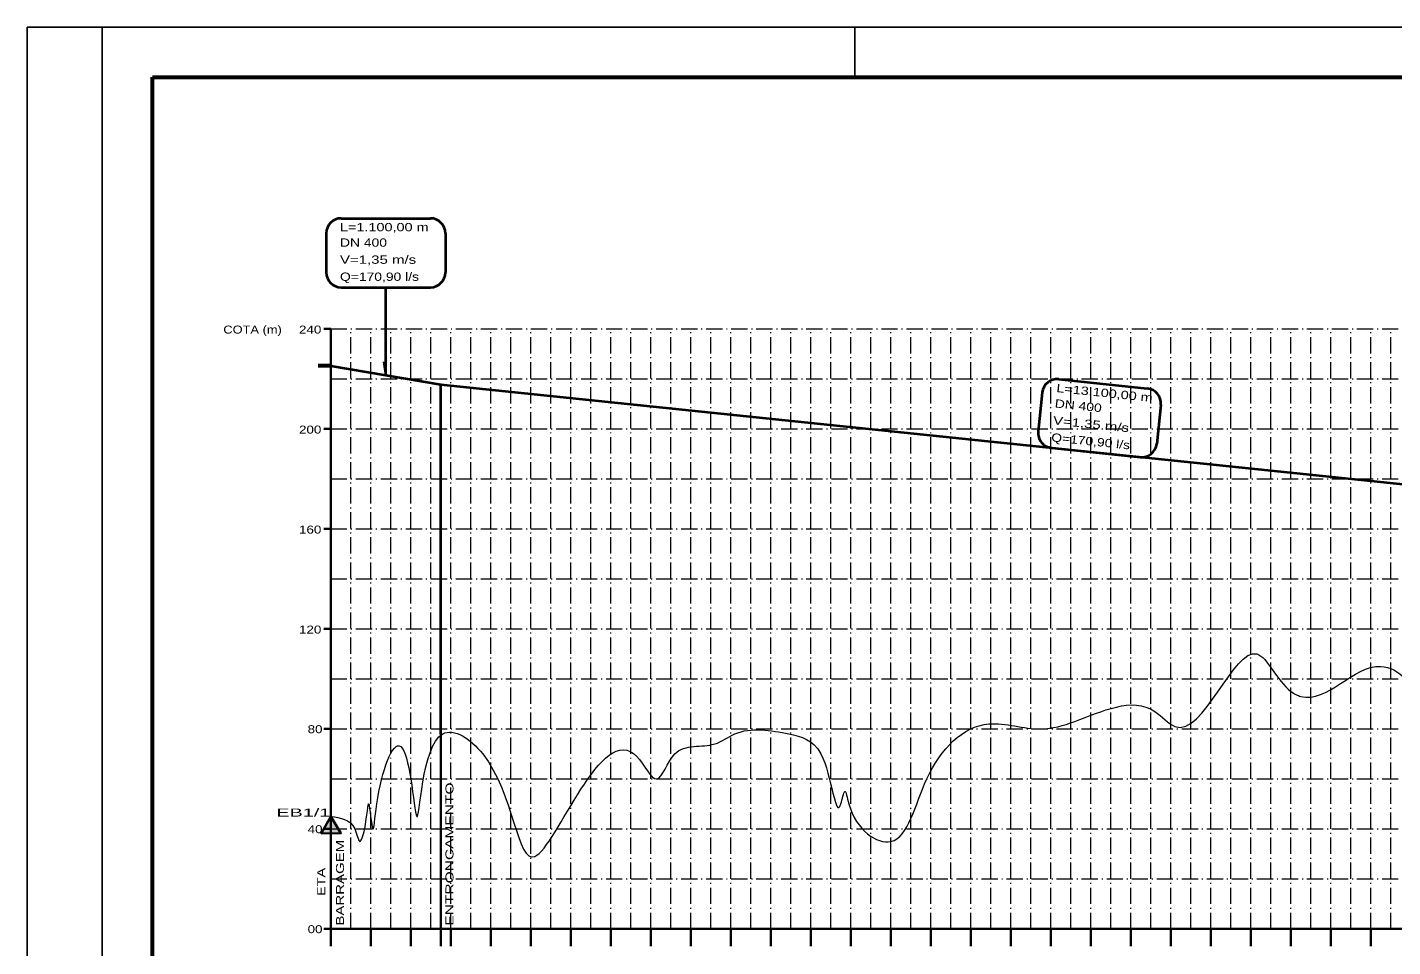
# Model space of a CAD drawing. Extents: x 0 to 1772, y 0 to 1188.
# Drawn here: x 0 to 546, y 820 to 1188 of the extents above; entities that cross this region are included whole.
import ezdxf
from ezdxf.enums import TextEntityAlignment as Align

# ---------------------------------------------------------------- set-up
doc = ezdxf.new("R2010")
doc.units = 0
doc.header["$LTSCALE"] = 1.3
doc.header["$PDMODE"] = 32
doc.header["$PDSIZE"] = 0.65
doc.linetypes.add('DOT_DASHED', pattern=[7.7, 5, -1.2, 0.3, -1.2])
for name, color, linetype, lineweight in [('1', 7, 'DOT_DASHED', 13), ('24', 7, 'Continuous', 35), ('55', 7, 'Continuous', 13), ('62', 7, 'Continuous', 13), ('63', 7, 'Continuous', 25), ('9', 7, 'Continuous', 40)]:
    doc.layers.add(name, color=color, linetype=linetype, lineweight=lineweight)

msp = doc.modelspace()

# ---------------------------------------------------------------- hatches: boundary and pattern name
at = {"layer": '62'}
msp.add_hatch(color=256, dxfattribs=at).paths.add_polyline_path([(121.273, 872.22), (125.219, 865.482), (117.41, 865.434)])

# ---------------------------------------------------------------- linework, layer by layer
at = {"layer": '1'}
for p, q in [((121.175, 1067.213), (1313.175, 1067.213)), ((129.175, 827.213), (129.175, 1067.213)), ((137.175, 827.213), (137.175, 1067.213)), ((145.175, 827.213), (145.175, 1067.213)), ((153.175, 827.213), (153.175, 1067.213)), ((161.175, 827.213), (161.175, 1067.213)), ((169.175, 827.213), (169.175, 1067.213)), ((177.175, 827.213), (177.175, 1067.213)), ((185.175, 827.213), (185.175, 1067.213)), ((193.175, 827.213), (193.175, 1067.213)), ((201.175, 827.213), (201.175, 1067.213)), ((209.175, 827.213), (209.175, 1067.213)), ((217.175, 827.213), (217.175, 1067.213)), ((225.175, 827.213), (225.175, 1067.213)), ((233.175, 827.213), (233.175, 1067.213)), ((241.175, 827.213), (241.175, 1067.213)), ((249.175, 827.213), (249.175, 1067.213)), ((257.175, 827.213), (257.175, 1067.213)), ((265.175, 827.213), (265.175, 1067.213)), ((273.175, 827.213), (273.175, 1067.213)), ((281.175, 827.213), (281.175, 1067.213)), ((289.175, 827.213), (289.175, 1067.213)), ((297.175, 827.213), (297.175, 1067.213)), ((305.175, 827.213), (305.175, 1067.213)), ((313.175, 827.213), (313.175, 1067.213)), ((321.175, 827.213), (321.175, 1067.213)), ((329.175, 827.213), (329.175, 1067.213)), ((337.175, 827.213), (337.175, 1067.213)), ((345.175, 827.213), (345.175, 1067.213)), ((353.175, 827.213), (353.175, 1067.213)), ((361.175, 827.213), (361.175, 1067.213)), ((369.175, 827.213), (369.175, 1067.213)), ((377.175, 827.213), (377.175, 1067.213)), ((385.175, 827.213), (385.175, 1067.213)), ((393.175, 827.213), (393.175, 1067.213)), ((401.175, 827.213), (401.175, 1067.213)), ((409.175, 827.213), (409.175, 1067.213)), ((417.175, 827.213), (417.175, 1067.213)), ((425.175, 827.213), (425.175, 1067.213)), ((433.175, 827.213), (433.175, 1067.213)), ((441.175, 827.213), (441.175, 1067.213)), ((449.175, 827.213), (449.175, 1067.213)), ((457.175, 827.213), (457.175, 1067.213)), ((465.175, 827.213), (465.175, 1067.213)), ((473.175, 827.213), (473.175, 1067.213)), ((481.175, 827.213), (481.175, 1067.213)), ((489.175, 827.213), (489.175, 1067.213)), ((497.175, 827.213), (497.175, 1067.213)), ((505.175, 827.213), (505.175, 1067.213)), ((513.175, 827.213), (513.175, 1067.213)), ((521.175, 827.213), (521.175, 1067.213)), ((529.175, 827.213), (529.175, 1067.213)), ((537.175, 827.213), (537.175, 1067.213)), ((545.175, 827.213), (545.175, 1067.213)), ((121.175, 1047.213), (1313.175, 1047.213)), ((121.175, 1027.213), (1313.175, 1027.213)), ((121.175, 1007.213), (1313.175, 1007.213)), ((121.175, 987.213), (1313.175, 987.213)), ((121.175, 967.213), (1313.175, 967.213)), ((121.175, 947.213), (1313.175, 947.213)), ((121.175, 927.213), (1313.175, 927.213)), ((129.175, 827.213), (129.175, 913.264)), ((137.175, 827.213), (137.175, 913.264)), ((145.175, 827.213), (145.175, 913.264)), ((153.175, 827.213), (153.175, 913.264)), ((161.175, 827.213), (161.175, 913.264)), ((169.175, 827.213), (169.175, 913.264)), ((121.175, 907.213), (173.611, 907.213)), ((121.175, 907.213), (1313.175, 907.213)), ((121.175, 887.213), (173.611, 887.213)), ((121.175, 887.213), (1313.175, 887.213)), ((121.175, 867.213), (173.611, 867.213)), ((121.175, 867.213), (1313.175, 867.213)), ((121.175, 847.213), (173.611, 847.213)), ((121.175, 847.213), (1313.175, 847.213))]:
    msp.add_line(p, q, dxfattribs=at)
at = {"layer": '55'}
msp.add_spline([(121.175, 872.213), (130.775, 867.213), (132.775, 862.213), (134.775, 867.213), (136.375, 877.213), (137.975, 867.213), (139.575, 877.213), (149.175, 900.213), (153.175, 887.213), (155.575, 872.213), (165.975, 905.213), (181.975, 897.213), (202.775, 856.213), (243.575, 896.213), (251.575, 887.213), (258.775, 897.213), (274.775, 901.213), (282.775, 905.213), (304.375, 905.213), (317.175, 897.213), (325.175, 877.213), (326.775, 882.213), (328.375, 877.213), (345.175, 862.213), (359.575, 887.213), (384.375, 909.213), (405.175, 907.213), (418.775, 910.213), (450.775, 914.213), (458.775, 908.213), (491.575, 937.213), (505.175, 922.213), (509.175, 920.213), (541.175, 932.213), (550.775, 927.213), (553.175, 924.213), (567.575, 939.213), (575.575, 941.213), (595.575, 927.213), (605.175, 937.213), (611.575, 927.213), (623.575, 917.213), (632.375, 930.213), (648.375, 912.213), (668.375, 877.213), (669.975, 872.213), (676.375, 892.213), (679.575, 887.213), (685.975, 881.213), (704.375, 869.213), (713.975, 871.213), (720.375, 869.213), (724.375, 877.213), (728.375, 873.213), (745.175, 877.213), (748.375, 879.213), (750.775, 877.213), (769.975, 893.213), (784.375, 872.213), (804.375, 897.213), (822.775, 905.213), (842.775, 881.213), (846.775, 887.213), (853.975, 880.213), (857.975, 882.213), (862.775, 887.213), (866.775, 872.213), (870.775, 885.213), (880.375, 882.213), (894.775, 907.213), (927.575, 924.213), (940.375, 910.213), (953.175, 920.213), (971.575, 914.213), (985.975, 922.213), (1018.775, 902.213), (1038.775, 922.213), (1086.775, 937.213), (1105.175, 920.213), (1113.175, 927.213), (1120.375, 921.213), (1141.175, 942.213), (1165.175, 923.213), (1169.975, 927.213), (1173.175, 920.213), (1183.928, 944.69), (1188.375, 946.213), (1193.175, 942.213)], degree=3, dxfattribs=at)
at = {"layer": '62', "lineweight": 35}
for p, q in [((121.175, 1067.213), (118.444, 1067.213)), ((121.006, 1067.213), (121.175, 1067.213)), ((121.175, 827.213), (121.175, 1067.213)), ((121.006, 1057.213), (121.175, 1057.213)), ((121.006, 1047.213), (121.175, 1047.213)), ((121.006, 1037.213), (121.175, 1037.213)), ((121.175, 1027.213), (118.444, 1027.213)), ((121.006, 1027.213), (121.175, 1027.213)), ((121.006, 1017.213), (121.175, 1017.213)), ((121.006, 1007.213), (121.175, 1007.213)), ((121.006, 997.213), (121.175, 997.213)), ((121.175, 987.213), (118.444, 987.213)), ((121.006, 987.213), (121.175, 987.213)), ((121.006, 977.213), (121.175, 977.213)), ((121.006, 967.213), (121.175, 967.213)), ((121.006, 957.213), (121.175, 957.213)), ((121.175, 947.213), (118.444, 947.213)), ((121.006, 947.213), (121.175, 947.213)), ((121.006, 937.213), (121.175, 937.213)), ((121.006, 927.213), (121.175, 927.213)), ((121.006, 917.213), (121.175, 917.213)), ((121.175, 827.213), (121.175, 913.264)), ((121.175, 907.213), (118.444, 907.213)), ((121.175, 907.213), (118.444, 907.213)), ((121.006, 907.213), (121.175, 907.213)), ((121.006, 907.213), (121.175, 907.213)), ((165.175, 827.213), (165.175, 905.164)), ((121.006, 897.213), (121.175, 897.213)), ((121.006, 897.213), (121.175, 897.213)), ((121.006, 887.213), (121.175, 887.213)), ((121.006, 887.213), (121.175, 887.213)), ((121.006, 877.213), (121.175, 877.213)), ((121.006, 877.213), (121.175, 877.213)), ((121.175, 867.213), (118.444, 867.213)), ((121.006, 867.213), (121.175, 867.213)), ((121.006, 867.213), (121.175, 867.213)), ((121.006, 857.213), (121.175, 857.213)), ((121.006, 857.213), (121.175, 857.213)), ((121.006, 847.213), (121.175, 847.213)), ((121.006, 847.213), (121.175, 847.213)), ((121.006, 837.213), (121.175, 837.213)), ((121.006, 837.213), (121.175, 837.213)), ((121.175, 827.213), (118.444, 827.213)), ((121.175, 827.213), (118.444, 827.213)), ((121.175, 827.213), (121.175, 820.386)), ((121.175, 827.213), (121.175, 820.386)), ((121.175, 827.213), (173.611, 827.213)), ((137.175, 827.213), (137.175, 820.386)), ((137.175, 827.213), (137.175, 820.386)), ((153.175, 827.213), (153.175, 820.386)), ((153.175, 827.213), (153.175, 820.386)), ((165.175, 827.213), (165.175, 820.386)), ((165.175, 827.213), (165.175, 820.386)), ((169.175, 827.213), (169.175, 820.386)), ((169.175, 827.213), (169.175, 820.386)), ((185.175, 827.213), (185.175, 820.386)), ((201.175, 827.213), (201.175, 820.386)), ((217.175, 827.213), (217.175, 820.386)), ((233.175, 827.213), (233.175, 820.386)), ((249.175, 827.213), (249.175, 820.386)), ((265.175, 827.213), (265.175, 820.386)), ((281.175, 827.213), (281.175, 820.386)), ((297.175, 827.213), (297.175, 820.386)), ((313.175, 827.213), (313.175, 820.386)), ((329.175, 827.213), (329.175, 820.386)), ((345.175, 827.213), (345.175, 820.386)), ((361.175, 827.213), (361.175, 820.386)), ((377.175, 827.213), (377.175, 820.386)), ((393.175, 827.213), (393.175, 820.386)), ((409.175, 827.213), (409.175, 820.386)), ((425.175, 827.213), (425.175, 820.386)), ((441.175, 827.213), (441.175, 820.386)), ((457.175, 827.213), (457.175, 820.386)), ((473.175, 827.213), (473.175, 820.386)), ((489.175, 827.213), (489.175, 820.386)), ((505.175, 827.213), (505.175, 820.386)), ((521.175, 827.213), (521.175, 820.386)), ((537.175, 827.213), (537.175, 820.386))]:
    msp.add_line(p, q, dxfattribs=at)
at = {"layer": '62'}
for p, q in [((121.006, 1065.213), (121.175, 1065.213)), ((121.006, 1063.213), (121.175, 1063.213)), ((121.006, 1061.213), (121.175, 1061.213)), ((121.006, 1059.213), (121.175, 1059.213)), ((121.006, 1055.213), (121.175, 1055.213)), ((121.006, 1053.213), (121.175, 1053.213)), ((121.006, 1051.213), (121.175, 1051.213)), ((121.006, 1049.213), (121.175, 1049.213)), ((121.006, 1045.213), (121.175, 1045.213)), ((121.006, 1043.213), (121.175, 1043.213)), ((121.006, 1041.213), (121.175, 1041.213)), ((121.006, 1039.213), (121.175, 1039.213)), ((121.006, 1035.213), (121.175, 1035.213)), ((121.006, 1033.213), (121.175, 1033.213)), ((121.006, 1031.213), (121.175, 1031.213)), ((121.006, 1029.213), (121.175, 1029.213)), ((121.006, 1025.213), (121.175, 1025.213)), ((121.006, 1023.213), (121.175, 1023.213)), ((121.006, 1021.213), (121.175, 1021.213)), ((121.006, 1019.213), (121.175, 1019.213)), ((121.006, 1015.213), (121.175, 1015.213)), ((121.006, 1013.213), (121.175, 1013.213)), ((121.006, 1011.213), (121.175, 1011.213)), ((121.006, 1009.213), (121.175, 1009.213)), ((121.006, 1005.213), (121.175, 1005.213)), ((121.006, 1003.213), (121.175, 1003.213)), ((121.006, 1001.213), (121.175, 1001.213)), ((121.006, 999.213), (121.175, 999.213)), ((121.006, 995.213), (121.175, 995.213)), ((121.006, 993.213), (121.175, 993.213)), ((121.006, 991.213), (121.175, 991.213)), ((121.006, 989.213), (121.175, 989.213)), ((121.006, 985.213), (121.175, 985.213)), ((121.006, 983.213), (121.175, 983.213)), ((121.006, 981.213), (121.175, 981.213)), ((121.006, 979.213), (121.175, 979.213)), ((121.006, 975.213), (121.175, 975.213)), ((121.006, 973.213), (121.175, 973.213)), ((121.006, 971.213), (121.175, 971.213)), ((121.006, 969.213), (121.175, 969.213)), ((121.006, 965.213), (121.175, 965.213)), ((121.006, 963.213), (121.175, 963.213)), ((121.006, 961.213), (121.175, 961.213)), ((121.006, 959.213), (121.175, 959.213)), ((121.006, 955.213), (121.175, 955.213)), ((121.006, 953.213), (121.175, 953.213)), ((121.006, 951.213), (121.175, 951.213)), ((121.006, 949.213), (121.175, 949.213)), ((121.006, 945.213), (121.175, 945.213)), ((121.006, 943.213), (121.175, 943.213)), ((121.006, 941.213), (121.175, 941.213)), ((121.006, 939.213), (121.175, 939.213)), ((121.006, 935.213), (121.175, 935.213)), ((121.006, 933.213), (121.175, 933.213)), ((121.006, 931.213), (121.175, 931.213)), ((121.006, 929.213), (121.175, 929.213)), ((121.006, 925.213), (121.175, 925.213)), ((121.006, 923.213), (121.175, 923.213)), ((121.006, 921.213), (121.175, 921.213)), ((121.006, 919.213), (121.175, 919.213)), ((121.006, 915.213), (121.175, 915.213)), ((121.006, 913.213), (121.175, 913.213)), ((121.006, 913.213), (121.175, 913.213)), ((121.006, 911.213), (121.175, 911.213)), ((121.006, 911.213), (121.175, 911.213)), ((121.006, 909.213), (121.175, 909.213)), ((121.006, 909.213), (121.175, 909.213)), ((121.006, 905.213), (121.175, 905.213)), ((121.006, 905.213), (121.175, 905.213)), ((121.006, 903.213), (121.175, 903.213)), ((121.006, 903.213), (121.175, 903.213)), ((121.006, 901.213), (121.175, 901.213)), ((121.006, 901.213), (121.175, 901.213)), ((121.006, 899.213), (121.175, 899.213)), ((121.006, 899.213), (121.175, 899.213)), ((121.006, 895.213), (121.175, 895.213)), ((121.006, 895.213), (121.175, 895.213)), ((121.006, 893.213), (121.175, 893.213)), ((121.006, 893.213), (121.175, 893.213)), ((121.006, 891.213), (121.175, 891.213)), ((121.006, 891.213), (121.175, 891.213)), ((121.006, 889.213), (121.175, 889.213)), ((121.006, 889.213), (121.175, 889.213)), ((121.006, 885.213), (121.175, 885.213)), ((121.006, 885.213), (121.175, 885.213)), ((121.006, 883.213), (121.175, 883.213)), ((121.006, 883.213), (121.175, 883.213)), ((121.006, 881.213), (121.175, 881.213)), ((121.006, 881.213), (121.175, 881.213)), ((121.006, 879.213), (121.175, 879.213)), ((121.006, 879.213), (121.175, 879.213)), ((121.006, 875.213), (121.175, 875.213)), ((121.006, 875.213), (121.175, 875.213)), ((121.006, 873.213), (121.175, 873.213)), ((121.006, 873.213), (121.175, 873.213)), ((121.006, 871.213), (121.175, 871.213)), ((121.006, 871.213), (121.175, 871.213)), ((121.006, 869.213), (121.175, 869.213)), ((121.006, 869.213), (121.175, 869.213)), ((121.006, 865.213), (121.175, 865.213)), ((121.006, 865.213), (121.175, 865.213)), ((121.006, 863.213), (121.175, 863.213)), ((121.006, 863.213), (121.175, 863.213)), ((121.006, 861.213), (121.175, 861.213)), ((121.006, 861.213), (121.175, 861.213)), ((121.006, 859.213), (121.175, 859.213)), ((121.006, 859.213), (121.175, 859.213)), ((121.006, 855.213), (121.175, 855.213)), ((121.006, 855.213), (121.175, 855.213)), ((121.006, 853.213), (121.175, 853.213)), ((121.006, 853.213), (121.175, 853.213)), ((121.006, 851.213), (121.175, 851.213)), ((121.006, 851.213), (121.175, 851.213)), ((121.006, 849.213), (121.175, 849.213)), ((121.006, 849.213), (121.175, 849.213)), ((121.006, 845.213), (121.175, 845.213)), ((121.006, 845.213), (121.175, 845.213)), ((121.006, 843.213), (121.175, 843.213)), ((121.006, 843.213), (121.175, 843.213)), ((121.006, 841.213), (121.175, 841.213)), ((121.006, 841.213), (121.175, 841.213)), ((121.006, 839.213), (121.175, 839.213)), ((121.006, 839.213), (121.175, 839.213)), ((121.006, 835.213), (121.175, 835.213)), ((121.006, 835.213), (121.175, 835.213)), ((121.006, 833.213), (121.175, 833.213)), ((121.006, 833.213), (121.175, 833.213)), ((121.006, 831.213), (121.175, 831.213)), ((121.006, 831.213), (121.175, 831.213)), ((121.006, 829.213), (121.175, 829.213)), ((121.006, 829.213), (121.175, 829.213))]:
    msp.add_line(p, q, dxfattribs=at)
at = {"layer": '62', "lineweight": 35}
msp.add_lwpolyline([(121.273, 872.22), (125.219, 865.482), (117.41, 865.434)], close=True, dxfattribs=at)
for points in [[(121.006, 867.213), (121.175, 867.213), (118.444, 867.213)], [(121.175, 827.213), (401.175, 827.213), (1193.175, 827.213)]]:
    msp.add_lwpolyline(points, dxfattribs=at)
at = {"layer": '63'}
for p, q in [((-0.167, 1187.873), (1771.833, 1187.873)), ((-0.167, -0.127), (-0.167, 1187.873)), ((29.833, 593.873), (29.833, 1187.873)), ((330.833, 1167.873), (330.833, 1187.873))]:
    msp.add_line(p, q, dxfattribs=at)
at = {"layer": '63', "lineweight": 60}
msp.add_line((121.175, 1052.49), (116.094, 1052.49), dxfattribs=at)
msp.add_lwpolyline([(49.833, 1167.873), (1751.833, 1167.873), (1751.833, 19.873), (49.833, 19.873)], close=True, dxfattribs=at)
at = {"layer": '9'}
for p, q in [((125.382, 1111.458), (161.016, 1111.458)), ((119.382, 1105.458), (119.382, 1089.848)), ((167.016, 1105.458), (167.016, 1089.848)), ((125.382, 1083.848), (161.016, 1083.848)), ((121.226, 1052.481), (165.173, 1044.943)), ((165.175, 905.164), (165.175, 1044.943)), ((165.176, 1044.943), (689.174, 990.643)), ((412.3, 1047.093), (447.744, 1043.42)), ((405.713, 1041.743), (404.104, 1026.216)), ((453.094, 1036.834), (451.485, 1021.306)), ((409.454, 1019.63), (444.898, 1015.957))]:
    msp.add_line(p, q, dxfattribs=at)
msp.add_lwpolyline([(142.368, 1054.147), (143.199, 1048.712), (143.199, 1083.848)], dxfattribs=at)
for centre, radius, start, end in [((125.382, 1105.458), 6, 90, 180), ((161.016, 1105.458), 6, 0, 90), ((125.382, 1089.848), 6, 180, 270), ((161.016, 1089.848), 6, 270, 0), ((121.219, 1052.441), 0.04, 80.26796, 184.98926), ((165.18, 1044.983), 0.04, 260.26796, 264.08379), ((411.681, 1041.125), 6, 84.08379, 174.08379), ((447.126, 1037.452), 6, 354.08379, 84.08379), ((410.072, 1025.598), 6, 174.08379, 264.08379), ((445.517, 1021.925), 6, 264.08379, 354.08379)]:
    msp.add_arc(centre, radius, start, end, dxfattribs=at)
msp.add_point((121.179, 1052.438), dxfattribs=at)

# ---------------------------------------------------------------- texts
at = {"layer": '24'}
for s, width, p in [('COTA (m)', 1.2, (101.613, 1065.357)), ('240', 1.25, (117.421, 1065.357)), ('200', 1.25, (117.421, 1025.357)), ('160', 1.25, (117.421, 985.357)), ('120', 1.25, (117.421, 945.357)), ('80', 1.25, (117.886, 905.512)), ('40', 1.25, (117.886, 865.512)), ('00', 1.25, (117.886, 825.512))]:
    msp.add_text(s, height=3.2, dxfattribs=dict(at, width=width)).set_placement(p, align=Align.RIGHT)
for s, width, p in [('ENTRONCAMENTO', 1.45, (170.264, 828.558)), ('BARRAGEM', 1.4, (126.479, 828.558)), ('ETA', 1.35, (118.975, 840.414))]:
    msp.add_text(s, height=3.2, rotation=90, dxfattribs=dict(at, width=width)).set_placement(p)
at = {"layer": '24', "width": 1.85}
msp.add_text('EB1/1', height=3.2, dxfattribs=at).set_placement((99.447, 872.169))
at = {"layer": '9'}
for s, width, p in [('L=1.100,00 m', 1.3, (124.867, 1106.279)), ('DN 400', 1.25, (124.867, 1100.1)), ('V=1,35 m/s', 1.35, (124.867, 1093.276)), ('Q=170,90 l/s', 1.25, (124.867, 1086.452))]:
    msp.add_text(s, height=3.319, dxfattribs=dict(at, width=width)).set_placement(p)
for s, width, p in [('L=13.100,00 m', 1.3, (411.254, 1041.995)), ('DN 400', 1.25, (410.617, 1035.848)), ('V=1,35 m/s', 1.35, (409.913, 1029.061)), ('Q=170,90 l/s', 1.25, (409.21, 1022.274))]:
    msp.add_text(s, height=3.319, rotation=354.084, dxfattribs=dict(at, width=width)).set_placement(p)

doc.saveas('drawing.dxf')
